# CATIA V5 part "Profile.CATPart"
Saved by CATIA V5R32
Part number: Profile
Bounding box of the stored display mesh (mm): x -58.221 to 95.108, y -67.694 to 79.25, z 0 to 0
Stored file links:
  D:\PROJECTS\Project 2022\CATIA V5 6R 2022\Resources\Part Files\c16_catia_v5_6r2022_prt\Point Curve Joint-(16-36)\Profile.CATPart
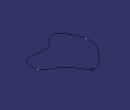
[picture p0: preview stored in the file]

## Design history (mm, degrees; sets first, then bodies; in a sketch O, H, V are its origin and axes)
Body1 (main body)
  Sketch1 on xy-plane, origin (0, 0, 0), H (1, 0, 0), V (0, 1, 0)
    spline S1 through (-56.936, -9.8228) (-36.2121, 48.255) (9.4222, 78.5932) (39.7622, 40.0274) (63.9393, 19.9693) (91.4937, -1.8468) (86.3206, -40.9294) (25.4678, -42.273) (-9.6787, -66.1719) (-56.936, -9.8228)
    point P1 (-56.936, -9.8228)
    point P2 (-56.936, -9.8228)
    coincidence: P1 P2
  Sketch2 on yz-plane, origin (0, 0, 0), H (0, 1, 0), V (0, 0, 1)
    line L1 (0, 84.1472) -> (0, 110.8669)
    point P1 (0, 84.1472)
    line L2 (0, 110.8669) -> (-22.6823, 110.8669)
    coincidence: P1 V
    vertical: L1 V
    horizontal: L2 H
  Point1: type OnCurve, Support Sketch1, RefPoint {extremum Reference Sketch1, Direction (1, 2, 3)}, Length 0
